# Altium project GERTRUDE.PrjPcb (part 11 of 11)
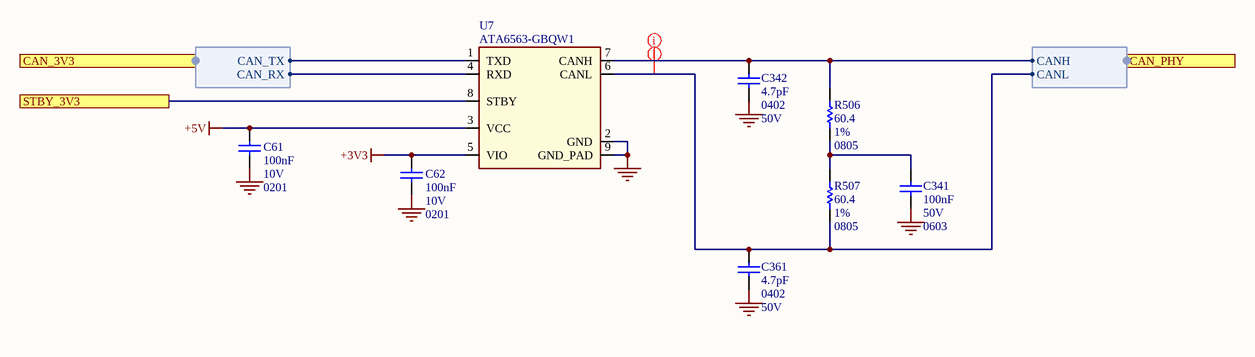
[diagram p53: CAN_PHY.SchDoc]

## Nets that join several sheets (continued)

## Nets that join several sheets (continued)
USB1_CAP_SSTX_P: HEADERS_JOMEGA (D18.1 D18.10 JOMEGA.18), PCIE_USB (C113.2)
USB1_D_N: HEADERS_JOMEGA (D18.5 D18.6 JOMEGA.26), PCIE_USB (U24.B18)
USB1_D_P: HEADERS_JOMEGA (D18.4 D18.7 JOMEGA.24), PCIE_USB (U24.A20)
USB1_SSRX_N: HEADERS_JOMEGA (D19.2 D19.9 JOMEGA.32), PCIE_USB (U24.B16)
USB1_SSRX_P: HEADERS_JOMEGA (D19.1 D19.10 JOMEGA.30), PCIE_USB (U24.A18)
USB2_CAP_SSTX_N: USB_USBA (D79.5 D79.6 J7.17), PCIE_USB (C284.2)
USB2_CAP_SSTX_P: USB_USBA (D79.4 D79.7 J7.18), PCIE_USB (C283.2)
USB2_D_N: USB_USBA (D78.1 D78.10 J7.11), PCIE_USB (U24.A13)
USB2_D_P: USB_USBA (D78.2 D78.9 J7.12), PCIE_USB (U24.B12)
USB2_SSRX_N: USB_USBA (D78.5 D78.6 J7.14), PCIE_USB (U24.A10)
USB2_SSRX_P: USB_USBA (D78.4 D78.7 J7.15), PCIE_USB (U24.B9)
USB3_CAP_SSTX_N: HEADERS_JOMEGA (D19.5 D19.6 JOMEGA.38), PCIE_USB (C290.2)
USB3_CAP_SSTX_P: HEADERS_JOMEGA (D19.4 D19.7 JOMEGA.36), PCIE_USB (C289.2)
USB3_D_N: HEADERS_JOMEGA (D20.2 D20.9 JOMEGA.44), PCIE_USB (U24.A27)
USB3_D_P: HEADERS_JOMEGA (D20.1 D20.10 JOMEGA.42), PCIE_USB (U24.B25)
USB3_SSRX_N: HEADERS_JOMEGA (D20.5 D20.6 JOMEGA.50), PCIE_USB (U24.A29)
USB3_SSRX_P: HEADERS_JOMEGA (D20.4 D20.7 JOMEGA.48), PCIE_USB (U24.B27)
USB4_CAP_SSTX_N: USB_USBA (D77.2 D77.9 J7.8), PCIE_USB (C298.2)
USB4_CAP_SSTX_P: USB_USBA (D77.1 D77.10 J7.9), PCIE_USB (C297.2)
USB4_D_N: USB_USBA (D76.1 D76.10 J7.2), PCIE_USB (U24.A5)
USB4_D_P: USB_USBA (D76.2 D76.9 J7.3), PCIE_USB (U24.B5)
USB4_SSRX_N: USB_USBA (D76.5 D76.6 J7.5), PCIE_USB (U24.A7)
USB4_SSRX_P: USB_USBA (D76.4 D76.7 J7.6), PCIE_USB (U24.B6)
USBC_CC1: USB_USBC (D73.5 D73.6 J1.A5), USB_PD_CONTROLLER (C40.2 U5.40)
USBC_CC2: USB_USBC (D72.5 D72.6 J1.B5), USB_PD_CONTROLLER (C41.2 U5.39)
USBC_SBU1: USB_USBC (D72.4 D72.7 J1.A8), USB_PD_CONTROLLER (R88.2 U5.38)
USBC_SBU2: USB_USBC (D73.4 D73.7 J1.B8), USB_PD_CONTROLLER (R89.2 U5.37)
USBC_SSRX1_N: USB (C51.2 R437.1), USB_USBC (D74.1 D74.10 J1.B10)
USBC_SSRX1_P: USB (C50.2 R436.1), USB_USBC (D74.2 D74.9 J1.B11)
USBC_SSRX2_N: USB (C53.2 R450.1), USB_USBC (D75.1 D75.10 J1.A10)
USBC_SSRX2_P: USB (C52.2 R449.1), USB_USBC (D75.2 D75.9 J1.A11)
USBC_SSTX1_N: USB (R452.1), USB_USBC (D74.5 D74.6 J1.A3)
USBC_SSTX1_P: USB (R451.1), USB_USBC (D74.4 D74.7 J1.A2)
USBC_SSTX2_N: USB (R454.1), USB_USBC (D75.5 D75.6 J1.B3)
USBC_SSTX2_P: USB (R453.1), USB_USBC (D75.4 D75.7 J1.B2)
WAKE_N_3V3: PCIE (R327.2), U_PCIE/U_TRANSLATOR_4CH (U21_5.10)
XRES: USB_PD_CONTROLLER (C49.2 R90.2 TP37.X U5.24), U_USB/U_USB_PD_CONTROLLER/T8CH_ (U33_1.14)

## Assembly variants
Assembled_ABX00163: not fitted C70 C91 C97 C105 C121 C126 C256 C293 C302 C303 C304 C308 C314 C328 C329 C330 C333 C342 C345 C347 C348 C353 C361 R1 R3 R4 R5 R12 R13 R14 R15 R17 R21 R31 R32 R33 R34 R35 R36 R37 R39 R40 R41 R42 R43 R51 R57 R58 R60 R62 R63 R64 R68 R80 R81 R82 R83 R91 R92 R115 R119 R133 R138 R155 R158 R159 R160 R163 R164 R175 R176 R177 R188 R189 R192 R210 R211 R212 R213 R216 R217 R218 R221 R233 R234 R236 R244 R246 R247 R250 R251 R252 R253 R254 R255 R256 R257 R267 R275 R286 R287 R293 R295 R296 R297 R298 R304 R308 R310 R311 R316 R318 R322 R343 R344 R345 R347 R348 R353 R358 R400 R413 R420 R421 R426 R427 R438 R464 R465 R471 R475 R478 R479 R489 R493 R494 R497 R501 R504 R510 R511 U30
